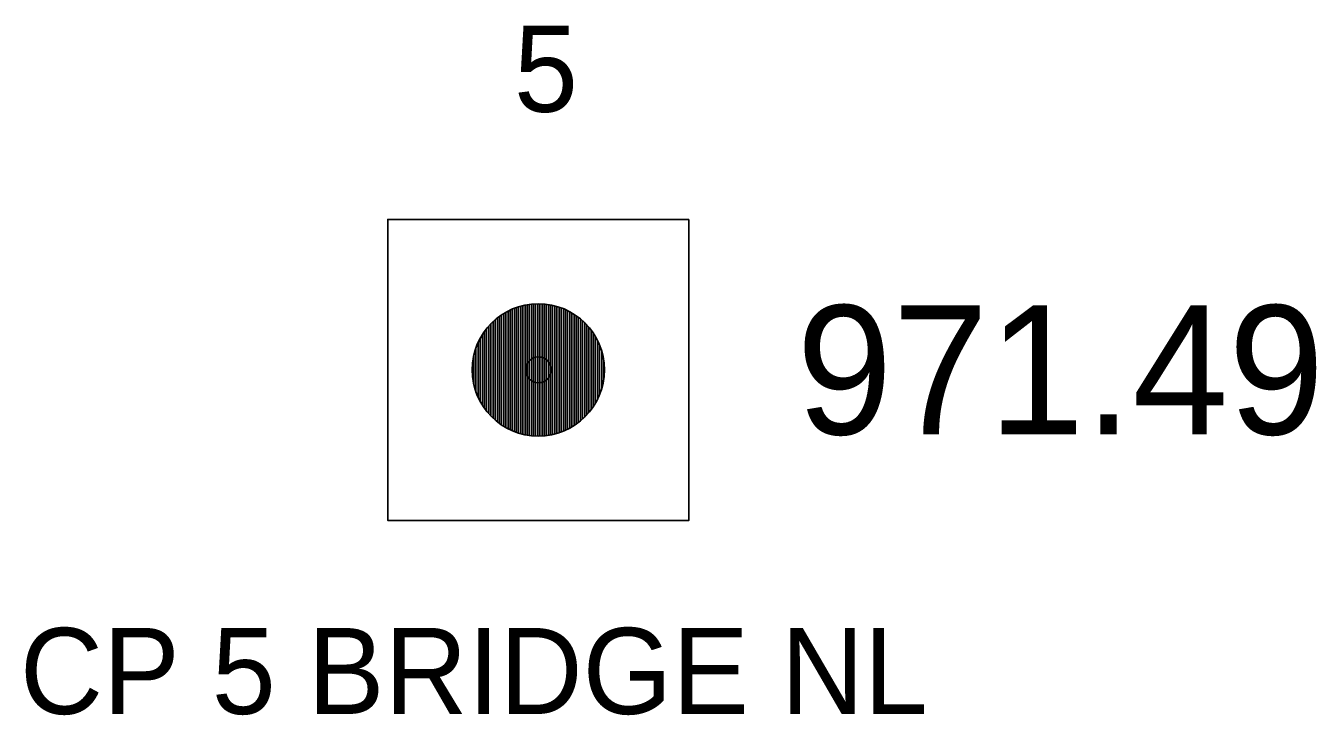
# Model space of a CAD drawing. Extents: x 1448136 to 1453623, y 1125056 to 1128842.
# Drawn here: x 1452377.5 to 1452392.5, y 1126624.71 to 1126632.72 of the extents above; entities that cross this region are included whole.
import ezdxf

# ---------------------------------------------------------------- set-up
doc = ezdxf.new("R2010")
doc.units = 0
for name, color, linetype in [('RD_HC_Survey', 7, 'Continuous'), ('RD_HC_Survey_ELEV', 7, 'Continuous'), ('RD_HC_Survey_txCode', 7, 'Continuous'), ('RD_SMD_Locator', 7, 'Continuous')]:
    doc.layers.add(name, color=color, linetype=linetype)

msp = doc.modelspace()

# ---------------------------------------------------------------- linework, layer by layer
at = {"layer": 'RD_HC_Survey'}
for p, q in [((1452383.103, 1126628.041), (1452383.103, 1126629.409)), ((1452383.127, 1126628.029), (1452383.127, 1126629.421)), ((1452383.152, 1126628.018), (1452383.152, 1126629.432)), ((1452383.177, 1126628.007), (1452383.177, 1126629.442)), ((1452383.202, 1126627.998), (1452383.202, 1126629.451)), ((1452383.226, 1126627.99), (1452383.226, 1126629.46)), ((1452383.251, 1126627.983), (1452383.251, 1126629.467)), ((1452383.276, 1126627.977), (1452383.276, 1126629.473)), ((1452383.301, 1126627.971), (1452383.301, 1126629.479)), ((1452383.325, 1126627.966), (1452383.325, 1126629.483)), ((1452383.35, 1126627.963), (1452383.35, 1126629.487)), ((1452383.375, 1126627.96), (1452383.375, 1126629.49)), ((1452383.4, 1126627.957), (1452383.4, 1126629.492)), ((1452383.424, 1126627.956), (1452383.424, 1126629.494)), ((1452383.449, 1126627.955), (1452383.449, 1126629.494)), ((1452383.474, 1126627.956), (1452383.474, 1126629.494)), ((1452383.499, 1126627.957), (1452383.499, 1126629.493)), ((1452383.523, 1126627.958), (1452383.523, 1126629.491)), ((1452383.548, 1126627.961), (1452383.548, 1126629.489)), ((1452383.573, 1126627.964), (1452383.573, 1126629.485)), ((1452383.598, 1126627.969), (1452383.598, 1126629.481)), ((1452383.622, 1126627.974), (1452383.622, 1126629.476)), ((1452383.647, 1126627.98), (1452383.647, 1126629.47)), ((1452383.672, 1126627.987), (1452383.672, 1126629.463)), ((1452383.697, 1126627.994), (1452383.697, 1126629.455)), ((1452383.721, 1126628.003), (1452383.721, 1126629.447)), ((1452383.746, 1126628.013), (1452383.746, 1126629.437)), ((1452383.771, 1126628.023), (1452383.771, 1126629.427)), ((1452383.796, 1126628.035), (1452383.796, 1126629.415)), ((1452382.905, 1126628.187), (1452382.905, 1126629.263)), ((1452382.929, 1126628.163), (1452382.929, 1126629.287)), ((1452382.954, 1126628.141), (1452382.954, 1126629.309)), ((1452382.979, 1126628.12), (1452382.979, 1126629.329)), ((1452383.004, 1126628.102), (1452383.004, 1126629.348)), ((1452383.028, 1126628.085), (1452383.028, 1126629.365)), ((1452383.053, 1126628.069), (1452383.053, 1126629.381)), ((1452383.078, 1126628.054), (1452383.078, 1126629.396)), ((1452383.82, 1126628.048), (1452383.82, 1126629.402)), ((1452383.845, 1126628.062), (1452383.845, 1126629.388)), ((1452383.87, 1126628.077), (1452383.87, 1126629.373)), ((1452383.895, 1126628.093), (1452383.895, 1126629.356)), ((1452383.919, 1126628.111), (1452383.919, 1126629.338)), ((1452383.944, 1126628.131), (1452383.944, 1126629.319)), ((1452383.969, 1126628.152), (1452383.969, 1126629.298)), ((1452383.994, 1126628.175), (1452383.994, 1126629.274)), ((1452382.806, 1126628.312), (1452382.806, 1126629.138)), ((1452382.83, 1126628.275), (1452382.83, 1126629.174)), ((1452382.855, 1126628.243), (1452382.855, 1126629.207)), ((1452382.88, 1126628.214), (1452382.88, 1126629.236)), ((1452384.018, 1126628.201), (1452384.018, 1126629.249)), ((1452384.043, 1126628.229), (1452384.043, 1126629.221)), ((1452384.068, 1126628.26), (1452384.068, 1126629.19)), ((1452384.093, 1126628.294), (1452384.093, 1126629.156)), ((1452384.117, 1126628.333), (1452384.117, 1126629.117)), ((1452382.731, 1126628.463), (1452382.731, 1126628.987)), ((1452382.756, 1126628.403), (1452382.756, 1126629.047)), ((1452382.781, 1126628.354), (1452382.781, 1126629.096)), ((1452384.142, 1126628.378), (1452384.142, 1126629.071)), ((1452384.167, 1126628.433), (1452384.167, 1126629.017)), ((1452382.707, 1126628.546), (1452382.707, 1126628.904)), ((1452384.192, 1126628.502), (1452384.192, 1126628.948)), ((1452384.216, 1126628.613), (1452384.216, 1126628.837))]:
    msp.add_line(p, q, dxfattribs=at)
msp.add_lwpolyline([(1452385.205, 1126630.475), (1452381.705, 1126630.475), (1452381.705, 1126626.975), (1452385.205, 1126626.975)], close=True, dxfattribs=at)
msp.add_circle((1452383.455, 1126628.725), 0.769, dxfattribs=at)
at = {"layer": 'RD_SMD_Locator'}
msp.add_circle((1452383.455, 1126628.725), 0.15, dxfattribs=at)

# ---------------------------------------------------------------- texts
at = {"layer": 'RD_HC_Survey_ELEV'}
msp.add_text('971.49', height=1.5, dxfattribs=at).set_placement((1452386.455, 1126627.975))
at = {"layer": 'RD_HC_Survey_txCode'}
for s, p in [('5', (1452383.172, 1126631.725)), ('CP 5 BRIDGE NL', (1452377.431, 1126624.725))]:
    msp.add_text(s, height=1, dxfattribs=at).set_placement(p)

doc.saveas('drawing.dxf')
